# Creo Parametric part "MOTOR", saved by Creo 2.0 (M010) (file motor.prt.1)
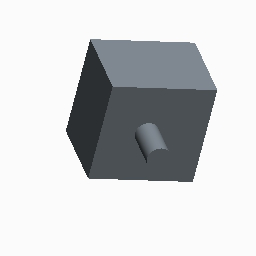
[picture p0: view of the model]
Units: Inch lbm Second (Pro/E Default); INCH, POUND, SECS

Created from: INLBS_PART_SOLID.PRT

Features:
  1. datum plane "RIGHT"
  2. datum plane "TOP"
  3. datum plane "FRONT"
  4. coordinate system
  5. sketch "Sketch 1"
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
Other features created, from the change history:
  extrusion "Extrude 1"
  sketch "Sketch 2"
  extrusion "Extrude 2"

Surfaces: 10 plane, 2 cylinder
